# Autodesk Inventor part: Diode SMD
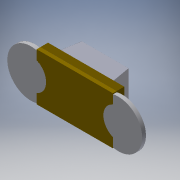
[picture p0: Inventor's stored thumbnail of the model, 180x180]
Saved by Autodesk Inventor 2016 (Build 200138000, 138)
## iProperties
Created: 2018-03
Part Number: Diode SMD
Material: Générique
Document SubType Name: Modeling
Designer: Bruno
Density: 1 g/cm^3
Appearance: Par défaut
Author: Bruno
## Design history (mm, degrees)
feature "Composite1"
body "Srf1"
